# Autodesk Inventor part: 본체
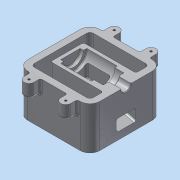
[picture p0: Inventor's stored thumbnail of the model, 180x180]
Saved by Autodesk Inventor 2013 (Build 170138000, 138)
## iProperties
Created: 2018-01
Part Number: 본체
Material: 알루미늄 6061
Document SubType Name: Modeling
Designer: dgall
Density: 2.71 g/cm^3
Mass: 1008.2 g
Surface Area: 833.849 cm^2
Volume: 372.03 cm^3
Author: dgall
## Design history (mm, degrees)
sketch "스케치1"
  geometry: L1 (-55, -55)-(55, -55); L2 (55, -55)-(55, 55); L3 (55, 55)-(-55, 55); L4 (-55, 55)-(-55, -55); L5 (-45, -45)-(45, -45); L6 (45, -45)-(45, 45); L7 (45, 45)-(-45, 45); L8 (-45, 45)-(-45, -45); 5 further points
  constraints: 16 end point, 4 midpoint, 4 parallel, 2 horizontal, 2 horizontal alignment, 2 perpendicular, 2 vertical alignment
  dimensions: "d0" = 110 distance of L2.end L3.end; "d2" = 110 distance of L1.end L2.end; "d3" = 10 distance between parallel lines of L3 L7; "d4" = 10 distance between parallel lines of L2 L6
extrude "돌출1" new body sketch "스케치1" distance "d5" = 65; taper "d6" = 0 deg
fillet "모깎기1" dims "d7" = 15, "d8" = 5
sketch "스케치2"
  geometry: L1 (40, 55)-(-40, 55) reference; L2 (-55, 40)-(-55, -40) reference; L3 (40, -45)-(-40, -45) reference; L4 (-35.5, 55)-(-35.5, 65); L5 (-20.5, 65)-(-20.5, 55); L6 (20.5, 55)-(20.5, 65); L7 (35.5, 65)-(35.5, 55); A1 r 7.5 centre (-28, 65) between (-20.5, 65) and (-35.5, 65); A2 r 7.5 centre (28, 65) between (35.5, 65) and (20.5, 65); 1 further point
  constraints: 8 end point, 4 point on circle, 4 point on line, 3 parallel, 3 perpendicular, 2 centre point, 2 tangent
  dimensions: "d13" = 27 distance from line of L2 A1.centre; "d14" = 15 diameter of A1; "d15" = 10 distance from line of L1 A1.centre; "d16" = 15 diameter of A2; "d17" = 56 distance of A1.centre A2.centre; "d18" = 10 distance from line of L1 A2.centre
extrude "돌출2" join sketch "스케치2" distance "d19" = 20; taper "d20" = 0 deg
fillet "모깎기4" dims "d23" = 3
fillet "모깎기5" dims "d24" = 3
sketch "스케치3"
  geometry: L1 (-55, 0)-(-55, 65) reference; L2 (-45, 65)-(-45, 0) reference; L3 (-45, 8.564)-(35, 30); L4 (-40, 0)-(-40, 65) reference; L5 (40, 0)-(-40, 0) reference; L6 (40, 65)-(40, 0) reference; L7 (-40, 65)-(40, 65) reference; L8 (35, 30)-(35, 65); L9 (35, 65)-(-55, 65); L10 (55, 65)-(55, 0) reference; L11 (-55, 65)-(-55, 8.564); L12 (-45, 8.564)-(-55, 8.564); 1 further point
  constraints: 10 end point, 3 perpendicular, 3 point on line
  dimensions: "d25" = 105 deg angle of L2 L3; "d26" = 30 distance from line of L5 L3.end; "d27" = 20 distance between parallel lines of L10 L8
extrude "돌출3" join sketch "스케치3" stored distance "d28" = 50; taper "d29" = 0 deg
sketch "스케치4"
  geometry: L1 (-55, 65)-(-40, 65) reference; L2 (-55, 65)-(-55, 57.5); L3 (-55, 57.5)-(-36, 57.5); L4 (-36, 57.5)-(-36, 49); L5 (-36, 49)-(-22, 49); L6 (-22, 49)-(-22, 45); L7 (-22, 45)-(25, 45); L8 (25, 45)-(25, 50); L9 (35, 65)-(-55, 65); L10 (25, 50)-(30, 50); L11 (30, 50)-(30, 65); 2 further points
  constraints: 20 end point, 6 parallel, 3 perpendicular, 1 collinear, 1 point on line, 1 vertical alignment
  dimensions: "d30" = 15 diameter of L3 L9; "d32" = 19 distance from line of L3.end L2; "d33" = 14 distance between parallel lines of L6 L4; "d34" = 32 diameter of L5 L9; "d35" = 40 diameter of L7 L9; "d37" = 47 distance between parallel lines of L8 L6; "d38" = 5 distance between parallel lines of L8 L11; "d39" = 30 diameter of L10 L9
revolve "회전1" sketch "스케치4" stored, may be unused: angle "d40" = 90 deg
sketch "스케치5"
  geometry: L1 (-55, 0)-(-55, 65) reference; L2 (-22, 45)-(25, 45) reference; L3 (35, 30)-(-45, 8.564) reference; L4 (-55, 29.061)-(-17, 39.243); L5 (-55, 11.061)-(20, 31.157); L6 (-22, 65)-(25, 65) reference; L7 (-17, 39.243)-(-17, 65); L8 (20, 31.157)-(20, 65); L9 (-22, 45)-(-22, 65) reference; 1 further point
  constraints: 8 end point, 4 point on line, 2 perpendicular, 1 parallel
  dimensions: "d41" = 5 distance between parallel lines of L3 L5; "d42" = 75 deg angle of L1 L4; "d43" = 18 distance of L5.start L4.start; "d45" = 5 distance between parallel lines of L9 L7; "d46" = 37 distance between parallel lines of L8 L7
extrude "돌출4" cut sketch "스케치5" stored distance "d47" = 30; taper "d48" = 0 deg
chamfer "모따기1" distance "d49" = 1; stored, may be unused: second distance "d50" = 2, angle "d51" = 45 deg
fillet "모깎기6" dims "d52" = 1
fillet "모깎기7" dims "d53" = 3
fillet "모깎기8" dims "d54" = 3
fillet "모깎기9" dims "d55" = 3
fillet "모깎기10" dims "d56" = 3
fillet "모깎기11" dims "d57" = 3
hole "구멍1" diameter "d60" = 3.242; stored, may be unused: countersink angle "d64" = 90 deg, drill point angle "d66" = 118 deg; dims "d58" = 10, "d59" = 10, "d61" = 9, "d62" = 4, "d63" = 2, "d65" = 11
sketch "스케치6"
  geometry: L1 (80, 0)-(0, 0) reference; 3 further points
  constraints: 1 midpoint, 1 vertical alignment, 1 other
  dimensions: "d67" = 20 distance of point (40, 0) point (40, -20)
feature "엠보싱1" sketch "스케치6" dims "d0" = 110, "d2" = 110, "d3" = 10, "d4" = 10, "d68" = 0.5, "d69" = 0
node "솔리드1"
mirror "대칭1"
mirror "대칭2"
mirror "대칭3"
node "투영된 루프1"
